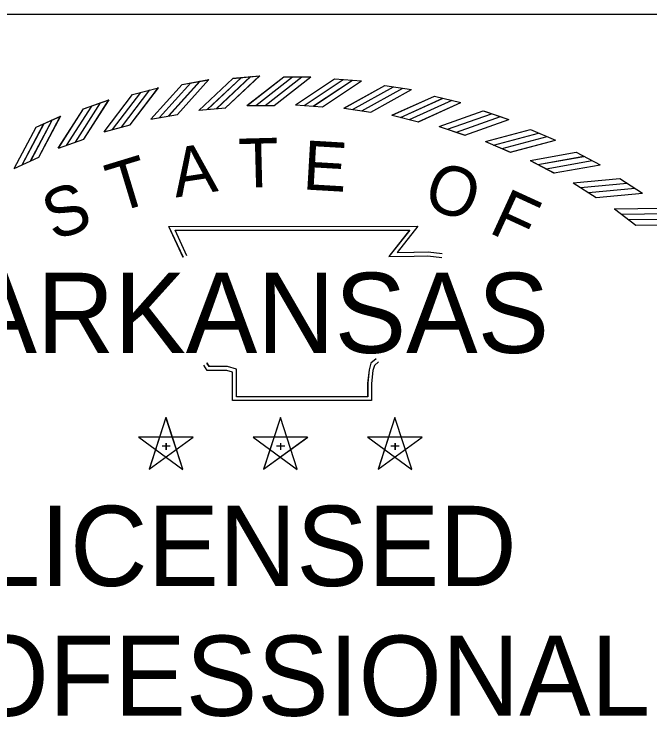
# Model space of a CAD drawing. Extents: x 0 to 1228740, y 0 to 152440.
# Drawn here: x 31.519 to 32.801, y 18.727 to 20.143 of the extents above; entities that cross this region are included whole.
import ezdxf

# ---------------------------------------------------------------- set-up
doc = ezdxf.new("R2010")
doc.units = 0
for name, color, linetype in [('R_Border', 7, 'Continuous'), ('STAMP_BOL', 7, 'Continuous'), ('STAMP_LKM', 7, 'Continuous'), ('STAMP_SPT', 7, 'Continuous')]:
    doc.layers.add(name, color=color, linetype=linetype)

msp = doc.modelspace()

# ---------------------------------------------------------------- linework, layer by layer
at = {"layer": 'R_Border'}
msp.add_line((29.1131, 20.1432), (33.4231, 20.1432), dxfattribs=at)
at = {"layer": 'STAMP_BOL'}
for p, q in [((31.9602, 20.0137), (32.0144, 20.0187)), ((32.0632, 20.0167), (32.1176, 20.0167)), ((31.8583, 20.0015), (31.9119, 20.011)), ((32.1651, 20.0126), (32.2194, 20.0086)), ((32.2668, 19.9994), (32.3206, 19.991)), ((31.7578, 19.981), (31.8105, 19.9948)), ((31.6594, 19.9522), (31.7107, 19.9703)), ((32.3671, 19.9779), (32.42, 19.965)), ((31.989, 19.9588), (32.0435, 19.9588)), ((32.0868, 19.9603), (32.1412, 19.9563)), ((31.8915, 19.9492), (31.9459, 19.9542)), ((32.1845, 19.9538), (32.2384, 19.9453)), ((32.4653, 19.9481), (32.5169, 19.9309)), ((31.5636, 19.9154), (31.6133, 19.9377)), ((31.7953, 19.9316), (31.849, 19.9411)), ((32.2813, 19.9392), (32.3343, 19.9263)), ((31.7008, 19.9061), (31.7535, 19.92)), ((32.3765, 19.9166), (32.4283, 19.8994)), ((32.5606, 19.9103), (32.6107, 19.8889)), ((31.6087, 19.8729), (31.6601, 19.891)), ((32.4696, 19.8863), (32.5197, 19.8648)), ((32.6525, 19.8648), (32.7006, 19.8393)), ((31.5197, 19.8321), (31.5694, 19.8545)), ((32.5598, 19.8484), (32.608, 19.8229)), ((32.6466, 19.8031), (32.6926, 19.7737)), ((32.7404, 19.8118), (32.7862, 19.7825)), ((32.7294, 19.7509), (32.7728, 19.7178)), ((31.8254, 19.3302), (31.7914, 19.2257)), ((31.8594, 19.2258), (31.8255, 19.3303)), ((32.0562, 19.3302), (32.0222, 19.2257)), ((32.0902, 19.2258), (32.0563, 19.3303)), ((32.287, 19.3302), (32.253, 19.2257)), ((32.321, 19.2258), (32.2871, 19.3303)), ((31.8803, 19.2903), (31.7705, 19.2904)), ((32.1111, 19.2903), (32.0013, 19.2904)), ((32.3419, 19.2903), (32.2321, 19.2904)), ((31.7706, 19.2903), (31.8594, 19.2257)), ((31.7915, 19.2258), (31.8804, 19.2903)), ((31.8255, 19.2786), (31.8255, 19.2648)), ((32.0014, 19.2903), (32.0902, 19.2257)), ((32.0223, 19.2258), (32.1112, 19.2903)), ((32.0563, 19.2786), (32.0563, 19.2648)), ((32.2322, 19.2903), (32.321, 19.2257)), ((32.2531, 19.2258), (32.342, 19.2903)), ((32.2871, 19.2786), (32.2871, 19.2648)), ((31.8176, 19.2728), (31.8339, 19.2728)), ((32.0484, 19.2728), (32.0647, 19.2728)), ((32.2792, 19.2728), (32.2955, 19.2728))]:
    msp.add_line(p, q, dxfattribs=at)
for points in [[(31.8915, 19.9491), (31.9601, 20.0136)], [(31.9089, 19.9506), (31.9776, 20.0151)], [(31.9277, 19.9527), (31.9963, 20.0172)], [(31.9458, 19.9542), (32.0144, 20.0187)], [(31.9889, 19.9588), (32.0631, 20.0167)], [(32.0064, 19.9586), (32.0806, 20.0165)], [(32.0253, 19.959), (32.0995, 20.0169)], [(32.0434, 19.9588), (32.1177, 20.0167)], [(31.7952, 19.9315), (31.8583, 20.0014)], [(31.8125, 19.9344), (31.8755, 20.0043)], [(31.831, 19.9381), (31.8941, 20.008)], [(31.8489, 19.9411), (31.912, 20.011)], [(32.0868, 19.9603), (32.165, 20.0126)], [(32.1042, 19.9588), (32.1825, 20.0111)], [(32.1231, 19.9579), (32.2014, 20.0102)], [(32.1412, 19.9564), (32.2194, 20.0087)], [(32.1844, 19.9537), (32.2668, 19.9994)], [(31.7177, 19.9103), (31.7748, 19.9852)], [(31.7359, 19.9155), (31.7929, 19.9904)], [(31.7534, 19.92), (31.8105, 19.9949)], [(32.2017, 19.9508), (32.284, 19.9965)], [(32.2204, 19.9483), (32.3028, 19.994)], [(32.2383, 19.9453), (32.3206, 19.991)], [(31.66, 19.8911), (31.7107, 19.9704)], [(31.7007, 19.906), (31.7578, 19.9809)], [(32.2812, 19.9391), (32.367, 19.9778)], [(32.2982, 19.9348), (32.384, 19.9735)], [(31.6252, 19.8785), (31.6759, 19.9578)], [(31.6429, 19.8852), (31.6936, 19.9645)], [(32.3166, 19.9308), (32.4025, 19.9695)], [(32.3342, 19.9263), (32.42, 19.965)], [(31.6086, 19.8728), (31.6593, 19.9521)], [(32.3765, 19.9166), (32.4652, 19.9481)], [(32.393, 19.9109), (32.4817, 19.9424)], [(31.5527, 19.8472), (31.5967, 19.9305)], [(31.5693, 19.8545), (31.6133, 19.9378)], [(32.4111, 19.9053), (32.4998, 19.9368)], [(32.4282, 19.8994), (32.517, 19.9309)], [(31.5196, 19.8321), (31.5636, 19.9153)], [(31.5357, 19.8391), (31.5796, 19.9224)], [(32.4695, 19.8863), (32.5605, 19.9103)], [(32.4856, 19.8792), (32.5766, 19.9033)], [(32.5031, 19.8722), (32.5941, 19.8962)], [(32.5197, 19.8649), (32.6107, 19.8889)], [(32.5598, 19.8483), (32.6525, 19.8648)], [(32.5752, 19.84), (32.6679, 19.8565)], [(32.5921, 19.8315), (32.6848, 19.848)], [(32.608, 19.8229), (32.7007, 19.8394)], [(32.6466, 19.8031), (32.7403, 19.8118)], [(32.6612, 19.7935), (32.755, 19.8023)], [(32.6774, 19.7837), (32.7711, 19.7924)], [(32.6925, 19.7738), (32.7863, 19.7825)], [(32.7293, 19.7509), (32.8235, 19.7518)], [(32.7431, 19.7401), (32.8373, 19.7411)], [(32.7584, 19.729), (32.8526, 19.7299)], [(31.8605, 19.6525), (31.8315, 19.7153), (32.3333, 19.7156), (32.2914, 19.663), (32.3255, 19.6634), (32.354, 19.6638), (32.3824, 19.6607)], [(32.7727, 19.7178), (32.8669, 19.7188)], [(31.8677, 19.6559), (31.8439, 19.7074), (32.3168, 19.7077), (32.2747, 19.6548), (32.3256, 19.6555), (32.3536, 19.6558), (32.3815, 19.6528)], [(32.2492, 19.4484), (32.2387, 19.4398), (32.235, 19.4263), (32.232, 19.3993), (32.232, 19.3721), (31.9678, 19.3721), (31.9678, 19.411), (31.9678, 19.4273), (31.9497, 19.4328), (31.9129, 19.4328), (31.9082, 19.44)], [(32.2542, 19.4422), (32.2457, 19.4353), (32.2428, 19.4249), (32.24, 19.3988), (32.24, 19.3642), (31.9599, 19.3642), (31.9599, 19.411), (31.9599, 19.4214), (31.9485, 19.4249), (31.9086, 19.4249), (31.9016, 19.4357)]]:
    msp.add_lwpolyline(points, dxfattribs=at)
at = {"layer": 'STAMP_LKM'}
for p, q in [((31.9603, 20.0136), (32.0145, 20.0186)), ((32.0633, 20.0167), (32.1177, 20.0167)), ((31.8585, 20.0015), (31.9121, 20.0109)), ((32.1653, 20.0126), (32.2195, 20.0086)), ((32.267, 19.9994), (32.3207, 19.9909)), ((31.758, 19.9809), (31.8106, 19.9948)), ((31.6595, 19.9522), (31.7108, 19.9703)), ((32.3672, 19.9778), (32.4201, 19.965)), ((31.9891, 19.9588), (32.0436, 19.9588)), ((32.087, 19.9603), (32.1413, 19.9563)), ((31.8917, 19.9492), (31.946, 19.9542)), ((32.1846, 19.9537), (32.2385, 19.9453)), ((32.4654, 19.9481), (32.517, 19.9309)), ((31.5638, 19.9154), (31.6134, 19.9377)), ((31.7954, 19.9316), (31.8491, 19.941)), ((32.2814, 19.9391), (32.3344, 19.9262)), ((31.7009, 19.9061), (31.7537, 19.9199)), ((32.3766, 19.9166), (32.4284, 19.8994)), ((32.5607, 19.9103), (32.6107, 19.8889)), ((31.6088, 19.8728), (31.6603, 19.891)), ((32.4697, 19.8863), (32.5198, 19.8648)), ((32.6526, 19.8648), (32.7007, 19.8393)), ((31.5198, 19.8321), (31.5696, 19.8545)), ((32.5599, 19.8484), (32.6081, 19.8228)), ((32.6467, 19.8031), (32.6926, 19.7737)), ((32.7405, 19.8118), (32.7863, 19.7825)), ((32.7295, 19.7509), (32.7728, 19.7178)), ((31.8256, 19.3302), (31.7915, 19.2258)), ((31.8595, 19.2258), (31.8257, 19.3303)), ((32.0564, 19.3302), (32.0223, 19.2258)), ((32.0903, 19.2258), (32.0564, 19.3303)), ((32.2871, 19.3302), (32.2531, 19.2258)), ((32.3211, 19.2258), (32.2872, 19.3303)), ((31.8805, 19.2903), (31.7706, 19.2904)), ((31.7707, 19.2903), (31.8595, 19.2257)), ((31.7917, 19.2258), (31.8806, 19.2903)), ((32.1112, 19.2903), (32.0014, 19.2904)), ((32.0015, 19.2903), (32.0903, 19.2257)), ((32.0225, 19.2258), (32.1114, 19.2903)), ((32.342, 19.2903), (32.2322, 19.2904)), ((32.2323, 19.2903), (32.3211, 19.2257)), ((32.2532, 19.2258), (32.3422, 19.2903)), ((31.8257, 19.2787), (31.8257, 19.2649)), ((32.0565, 19.2787), (32.0565, 19.2649)), ((32.2873, 19.2787), (32.2873, 19.2649)), ((31.8178, 19.2728), (31.8341, 19.2728)), ((32.0485, 19.2728), (32.0649, 19.2728)), ((32.2793, 19.2728), (32.2957, 19.2728))]:
    msp.add_line(p, q, dxfattribs=at)
for points in [[(31.8916, 19.9491), (31.9602, 20.0136)], [(31.9091, 19.9506), (31.9777, 20.015)], [(31.9279, 19.9527), (31.9965, 20.0172)], [(31.9459, 19.9542), (32.0145, 20.0187)], [(31.989, 19.9587), (32.0633, 20.0166)], [(32.0065, 19.9586), (32.0808, 20.0165)], [(32.0254, 19.959), (32.0997, 20.0169)], [(32.0436, 19.9588), (32.1178, 20.0167)], [(31.7954, 19.9315), (31.8584, 20.0014)], [(31.8126, 19.9344), (31.8757, 20.0043)], [(31.8312, 19.9381), (31.8942, 20.008)], [(31.849, 19.9411), (31.9121, 20.011)], [(32.0869, 19.9603), (32.1652, 20.0126)], [(32.1043, 19.9588), (32.1826, 20.0111)], [(32.1232, 19.9578), (32.2015, 20.0101)], [(32.1413, 19.9564), (32.2196, 20.0086)], [(32.1845, 19.9537), (32.2669, 19.9994)], [(31.7178, 19.9103), (31.7749, 19.9852)], [(31.736, 19.9155), (31.7931, 19.9904)], [(31.7536, 19.92), (31.8106, 19.9948)], [(32.2018, 19.9508), (32.2841, 19.9965)], [(32.2205, 19.9483), (32.3029, 19.9939)], [(32.2384, 19.9453), (32.3208, 19.991)], [(31.6602, 19.891), (31.7109, 19.9704)], [(31.7009, 19.906), (31.7579, 19.9809)], [(32.2813, 19.9391), (32.3671, 19.9778)], [(32.2983, 19.9348), (32.3841, 19.9735)], [(31.6254, 19.8785), (31.6761, 19.9578)], [(31.643, 19.8852), (31.6937, 19.9645)], [(32.3168, 19.9307), (32.4026, 19.9694)], [(32.3343, 19.9263), (32.4201, 19.965)], [(31.6088, 19.8728), (31.6595, 19.9521)], [(32.3766, 19.9166), (32.4653, 19.948)], [(32.3931, 19.9109), (32.4818, 19.9424)], [(31.5529, 19.8472), (31.5969, 19.9305)], [(31.5695, 19.8545), (31.6135, 19.9378)], [(32.4112, 19.9053), (32.4999, 19.9368)], [(32.4283, 19.8994), (32.517, 19.9309)], [(31.5198, 19.8321), (31.5638, 19.9153)], [(31.5358, 19.8391), (31.5798, 19.9223)], [(32.4696, 19.8862), (32.5606, 19.9103)], [(32.4856, 19.8792), (32.5767, 19.9033)], [(32.5032, 19.8722), (32.5942, 19.8962)], [(32.5198, 19.8649), (32.6108, 19.8889)], [(32.5598, 19.8483), (32.6525, 19.8648)], [(32.5752, 19.84), (32.6679, 19.8564)], [(32.5921, 19.8315), (32.6848, 19.848)], [(32.6081, 19.8229), (32.7008, 19.8393)], [(32.6466, 19.8031), (32.7404, 19.8118)], [(32.6613, 19.7935), (32.755, 19.8023)], [(32.6774, 19.7837), (32.7712, 19.7924)], [(32.6926, 19.7738), (32.7863, 19.7825)], [(32.7294, 19.7509), (32.8235, 19.7518)], [(32.7432, 19.7401), (32.8374, 19.7411)], [(32.7585, 19.729), (32.8526, 19.7299)], [(31.8606, 19.6525), (31.8316, 19.7153), (32.3334, 19.7156), (32.2915, 19.663), (32.3256, 19.6634), (32.3541, 19.6638), (32.3825, 19.6607)], [(32.7728, 19.7178), (32.8669, 19.7188)], [(31.8678, 19.6559), (31.844, 19.7074), (32.3169, 19.7077), (32.2748, 19.6548), (32.3257, 19.6555), (32.3537, 19.6558), (32.3816, 19.6528)], [(32.2493, 19.4484), (32.2388, 19.4398), (32.2351, 19.4264), (32.2322, 19.3993), (32.2322, 19.3721), (31.9679, 19.3721), (31.9679, 19.411), (31.9679, 19.4273), (31.9498, 19.4328), (31.9131, 19.4328), (31.9084, 19.44)], [(32.2543, 19.4423), (32.2458, 19.4353), (32.2429, 19.4249), (32.2401, 19.3989), (32.2401, 19.3642), (31.96, 19.3642), (31.96, 19.411), (31.96, 19.4214), (31.9486, 19.4249), (31.9088, 19.4249), (31.9017, 19.4357)]]:
    msp.add_lwpolyline(points, dxfattribs=at)
at = {"layer": 'STAMP_SPT'}
for p, q in [((31.9602, 20.0137), (32.0144, 20.0186)), ((32.0633, 20.0167), (32.1177, 20.0167)), ((31.8584, 20.0015), (31.912, 20.0109)), ((32.1652, 20.0126), (32.2194, 20.0086)), ((32.2669, 19.9994), (32.3206, 19.9909)), ((31.7579, 19.981), (31.8105, 19.9948)), ((31.6595, 19.9522), (31.7108, 19.9703)), ((32.3671, 19.9778), (32.42, 19.965)), ((31.989, 19.9588), (32.0435, 19.9588)), ((32.0869, 19.9603), (32.1413, 19.9563)), ((31.8916, 19.9492), (31.9459, 19.9542)), ((32.1845, 19.9538), (32.2384, 19.9453)), ((32.4653, 19.9481), (32.5169, 19.9309)), ((31.5637, 19.9154), (31.6134, 19.9377)), ((31.7953, 19.9316), (31.849, 19.941)), ((32.2813, 19.9392), (32.3343, 19.9263)), ((31.7008, 19.9061), (31.7536, 19.9199)), ((32.3766, 19.9166), (32.4283, 19.8994)), ((32.5606, 19.9103), (32.6107, 19.8889)), ((31.6088, 19.8729), (31.6602, 19.891)), ((32.4696, 19.8863), (32.5198, 19.8648)), ((32.6526, 19.8648), (32.7006, 19.8393)), ((31.5198, 19.8321), (31.5695, 19.8545)), ((32.5598, 19.8484), (32.608, 19.8229)), ((32.6466, 19.8031), (32.6926, 19.7737)), ((32.7404, 19.8119), (32.7862, 19.7825)), ((32.7294, 19.7509), (32.7727, 19.7178)), ((31.8255, 19.3302), (31.7915, 19.2258)), ((31.8594, 19.2258), (31.8256, 19.3303)), ((32.0563, 19.3302), (32.0222, 19.2258)), ((32.0902, 19.2258), (32.0564, 19.3303)), ((32.2871, 19.3302), (32.253, 19.2258)), ((32.321, 19.2258), (32.2871, 19.3303)), ((31.8804, 19.2904), (31.7705, 19.2905)), ((31.7706, 19.2904), (31.8594, 19.2257)), ((31.7916, 19.2258), (31.8805, 19.2903)), ((32.1112, 19.2904), (32.0013, 19.2905)), ((32.0014, 19.2904), (32.0902, 19.2257)), ((32.0224, 19.2258), (32.1113, 19.2903)), ((32.3419, 19.2904), (32.2321, 19.2905)), ((32.2322, 19.2904), (32.321, 19.2257)), ((32.2532, 19.2258), (32.3421, 19.2903)), ((31.8256, 19.2787), (31.8256, 19.2649)), ((32.0564, 19.2787), (32.0564, 19.2649)), ((32.2872, 19.2787), (32.2872, 19.2649)), ((31.8177, 19.2728), (31.834, 19.2728)), ((32.0485, 19.2728), (32.0648, 19.2728)), ((32.2793, 19.2728), (32.2956, 19.2728))]:
    msp.add_line(p, q, dxfattribs=at)
for points in [[(31.8916, 19.9491), (31.9602, 20.0136)], [(31.909, 19.9506), (31.9776, 20.015)], [(31.9278, 19.9527), (31.9964, 20.0172)], [(31.9458, 19.9542), (32.0145, 20.0187)], [(31.9889, 19.9587), (32.0632, 20.0166)], [(32.0065, 19.9586), (32.0807, 20.0165)], [(32.0254, 19.959), (32.0996, 20.0169)], [(32.0435, 19.9588), (32.1177, 20.0167)], [(31.7953, 19.9315), (31.8583, 20.0014)], [(31.8126, 19.9344), (31.8756, 20.0043)], [(31.8311, 19.9381), (31.8941, 20.008)], [(31.849, 19.9411), (31.912, 20.011)], [(32.0868, 19.9603), (32.1651, 20.0126)], [(32.1043, 19.9588), (32.1825, 20.0111)], [(32.1231, 19.9579), (32.2014, 20.0101)], [(32.1412, 19.9564), (32.2195, 20.0087)], [(32.1845, 19.9537), (32.2668, 19.9994)], [(31.7178, 19.9103), (31.7748, 19.9852)], [(31.7359, 19.9155), (31.793, 19.9904)], [(31.7535, 19.92), (31.8106, 19.9948)], [(32.2017, 19.9508), (32.2841, 19.9965)], [(32.2205, 19.9483), (32.3028, 19.994)], [(32.2383, 19.9453), (32.3207, 19.991)], [(31.6601, 19.8911), (31.7108, 19.9704)], [(31.7008, 19.906), (31.7579, 19.9809)], [(32.2812, 19.9391), (32.3671, 19.9778)], [(32.2982, 19.9348), (32.384, 19.9735)], [(31.6253, 19.8785), (31.676, 19.9578)], [(31.643, 19.8852), (31.6937, 19.9645)], [(32.3167, 19.9308), (32.4025, 19.9695)], [(32.3342, 19.9263), (32.4201, 19.965)], [(31.6087, 19.8728), (31.6594, 19.9521)], [(32.3765, 19.9166), (32.4652, 19.9481)], [(32.393, 19.9109), (32.4818, 19.9424)], [(31.5528, 19.8472), (31.5968, 19.9305)], [(31.5694, 19.8545), (31.6134, 19.9378)], [(32.4111, 19.9053), (32.4998, 19.9368)], [(32.4282, 19.8994), (32.517, 19.9309)], [(31.5197, 19.8321), (31.5637, 19.9153)], [(31.5358, 19.8391), (31.5797, 19.9224)], [(32.4695, 19.8863), (32.5606, 19.9103)], [(32.4856, 19.8792), (32.5766, 19.9033)], [(32.5031, 19.8722), (32.5941, 19.8962)], [(32.5197, 19.8649), (32.6107, 19.8889)], [(32.5598, 19.8483), (32.6525, 19.8648)], [(32.5752, 19.84), (32.6679, 19.8565)], [(32.5921, 19.8315), (32.6848, 19.848)], [(32.608, 19.8229), (32.7007, 19.8394)], [(32.6466, 19.8031), (32.7403, 19.8119)], [(32.6612, 19.7935), (32.755, 19.8023)], [(32.6774, 19.7837), (32.7711, 19.7924)], [(32.6925, 19.7738), (32.7863, 19.7825)], [(32.7293, 19.7509), (32.8235, 19.7518)], [(32.7431, 19.7401), (32.8373, 19.7411)], [(32.7584, 19.729), (32.8526, 19.7299)], [(31.8606, 19.6525), (31.8316, 19.7154), (32.3333, 19.7156), (32.2914, 19.663), (32.3255, 19.6634), (32.354, 19.6638), (32.3824, 19.6607)], [(32.7727, 19.7179), (32.8669, 19.7188)], [(31.8678, 19.6559), (31.844, 19.7074), (32.3169, 19.7077), (32.2748, 19.6548), (32.3256, 19.6555), (32.3536, 19.6558), (32.3816, 19.6528)], [(32.2493, 19.4484), (32.2387, 19.4399), (32.235, 19.4264), (32.2321, 19.3993), (32.2321, 19.3721), (31.9679, 19.3721), (31.9679, 19.411), (31.9679, 19.4273), (31.9497, 19.4328), (31.913, 19.4328), (31.9083, 19.4401)], [(32.2543, 19.4423), (32.2457, 19.4353), (32.2429, 19.4249), (32.24, 19.3989), (32.24, 19.3642), (31.9599, 19.3642), (31.9599, 19.411), (31.9599, 19.4214), (31.9486, 19.4249), (31.9087, 19.4249), (31.9016, 19.4357)]]:
    msp.add_lwpolyline(points, dxfattribs=at)

# ---------------------------------------------------------------- texts
at = {"layer": 'STAMP_BOL'}
for s, rotation, p in [('T', 1.4789, (31.973, 19.793)), ('E', 356.672, (32.0997, 19.79)), ('A', 8.6788, (31.8452, 19.7733)), ('T', 16.9015, (31.725, 19.742)), ('O', 341.2218, (32.3401, 19.7561)), ('S', 19.7726, (31.5991, 19.6855)), ('F', 335.3628, (32.4735, 19.7039))]:
    msp.add_text(s, height=0.099, rotation=rotation, dxfattribs=at).set_placement(p)
for s, p in [('ARKANSAS', (31.4213, 19.4603)), ('LICENSED', (31.452, 18.9907)), ('PROFESSIONAL', (31.1212, 18.7291))]:
    msp.add_text(s, height=0.16156, dxfattribs=at).set_placement(p)
at = {"layer": 'STAMP_LKM'}
for s, rotation, p in [('T', 1.4789, (31.9732, 19.793)), ('E', 356.672, (32.0998, 19.79)), ('A', 8.6788, (31.8453, 19.7733)), ('T', 16.9015, (31.7251, 19.742)), ('O', 341.2218, (32.3402, 19.7561)), ('S', 19.7726, (31.5993, 19.6855)), ('F', 335.3628, (32.4736, 19.7039))]:
    msp.add_text(s, height=0.099, rotation=rotation, dxfattribs=at).set_placement(p)
for s, height, p in [('ARKANSAS', 0.16155, (31.4214, 19.4603)), ('LICENSED', 0.16155, (31.4522, 18.9908)), ('PROFESSIONAL', 0.161547, (31.1214, 18.7292))]:
    msp.add_text(s, height=height, dxfattribs=at).set_placement(p)
at = {"layer": 'STAMP_SPT'}
for s, rotation, p in [('T', 1.4789, (31.9731, 19.793)), ('E', 356.672, (32.0998, 19.79)), ('A', 8.6788, (31.8453, 19.7733)), ('T', 16.9015, (31.7251, 19.742)), ('O', 341.2218, (32.3401, 19.7561)), ('S', 19.7726, (31.5992, 19.6855)), ('F', 335.3628, (32.4735, 19.7039))]:
    msp.add_text(s, height=0.099, rotation=rotation, dxfattribs=at).set_placement(p)
for s, height, p in [('ARKANSAS', 0.16155, (31.4214, 19.4603)), ('LICENSED', 0.16155, (31.4521, 18.9908)), ('PROFESSIONAL', 0.161547, (31.1214, 18.7292))]:
    msp.add_text(s, height=height, dxfattribs=at).set_placement(p)

doc.saveas('drawing.dxf')
